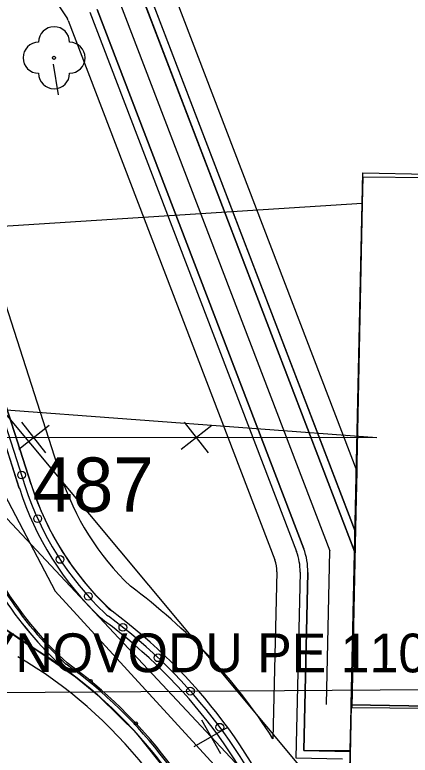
# Model space of a CAD drawing. Extents: x -643342 to -638635, y -1201752 to -1189948.
# Drawn here: x -639485.41 to -639472.65, y -1192704.29 to -1192680.44 of the extents above; entities that cross this region are included whole.
import ezdxf

# ---------------------------------------------------------------- set-up
doc = ezdxf.new("R2010")
doc.units = 0
for name, color, linetype in [('-zbytky_kruháče', 7, 'Continuous'), ('42', 7, 'Continuous'), ('IS_EL_NN_NADZEMNÍ', 7, 'Continuous'), ('IS_EL_NN_PODZEMNÍ', 7, 'Continuous'), ('K-HRANICE_KN', 7, 'Continuous'), ('K-SLUCKOVE CARY', 7, 'Continuous'), ('K-ČÍSLA_PARCEL', 7, 'Continuous'), ('N-CHODNIK', 7, 'Continuous'), ('N-CHODNIK-PŘÍMĚTICE', 7, 'Continuous'), ('N-OBVOD STAVBY 06', 7, 'Continuous'), ('N-oploceni', 7, 'Continuous'), ('N-rusene_vedeni', 7, 'Continuous'), ('N-SILNICE', 7, 'Continuous'), ('N-SRAFY_PLOCHY', 7, 'Continuous'), ('N-vo', 7, 'Continuous'), ('N-ZDI', 7, 'Continuous'), ('N-úprava plochu u obecního úřadu', 7, 'Continuous'), ('tomaštík - Džuganovi - Vrstva 36', 7, 'Continuous'), ('Z-budovy', 7, 'Continuous'), ('Z-hrany_a_čáry', 7, 'Continuous'), ('Z-stromy', 7, 'Continuous')]:
    doc.layers.add(name, color=color, linetype=linetype)

# ---------------------------------------------------------------- blocks, each defined once
blk = doc.blocks.new('zs')
at = {"layer": 'N-oploceni'}
blk.add_circle((0, 0), 0.05, dxfattribs=at)

msp = doc.modelspace()

# ---------------------------------------------------------------- linework, layer by layer
at = {"layer": '-zbytky_kruháče'}
msp.add_arc((-639492.588, -1192713.663), 14.5, 16.3969, 59.8841, dxfattribs=at)
at = {"layer": '42'}
msp.add_line((-639511.045, -1192702.433), (-639465.369, -1192702.13), dxfattribs=at)
at = {"layer": 'IS_EL_NN_NADZEMNÍ'}
msp.add_line((-639467.47, -1192716.07), (-639488.19, -1192693.98), dxfattribs=at)
msp.add_lwpolyline([(-639485.829, -1192693.153), (-639467.777, -1192714.748)], dxfattribs=at)
at = {"layer": 'IS_EL_NN_PODZEMNÍ'}
msp.add_line((-639489.5, -1192694.06), (-639474.67, -1192694.04), dxfattribs=at)
for points in [[(-639485.819, -1192693.156), (-639473.733, -1192694.06)], [(-639474.67, -1192694.04), (-639473.733, -1192694.06)]]:
    msp.add_lwpolyline(points, dxfattribs=at)
at = {"layer": 'K-HRANICE_KN'}
for p, q in [((-639474.18, -1192685.67), (-639474.2, -1192686.51)), ((-639463.27, -1192685.77), (-639474.18, -1192685.67)), ((-639474.2, -1192686.51), (-639490.92, -1192687.58))]:
    msp.add_line(p, q, dxfattribs=at)
at = {"layer": 'K-SLUCKOVE CARY'}
for p, q in [((-639474.2, -1192686.51), (-639474.54, -1192702.75)), ((-639474.54, -1192702.75), (-639457.62, -1192702.9))]:
    msp.add_line(p, q, dxfattribs=at)
at = {"layer": 'N-CHODNIK'}
for p, q in [((-639483.994, -1192683.015), (-639484.163, -1192682.029)), ((-639474.553, -1192702.67), (-639474.724, -1192710.703)), ((-639474.553, -1192702.67), (-639471.552, -1192702.72))]:
    msp.add_line(p, q, dxfattribs=at)
at = {"layer": 'N-CHODNIK-PŘÍMĚTICE'}
msp.add_line((-639488.992, -1192684.114), (-639485.26, -1192695.692), dxfattribs=at)
for centre, radius, start, end in [((-639475.742, -1192692.624), 10, 197.8667, 226.3544), ((-639475.742, -1192692.624), 12, 197.8667, 227.5242), ((-639475.742, -1192692.624), 11.85, 197.8667, 227.5242), ((-639481.678, -1192698.847), 1, 226.3544, 233.6318), ((-639481.678, -1192698.847), 1.4, 226.3544, 233.6318), ((-639492.588, -1192713.663), 17, 20.3626, 53.6318)]:
    msp.add_arc(centre, radius, start, end, dxfattribs=at)
at = {"layer": 'N-OBVOD STAVBY 06'}
msp.add_line((-639470.553, -1192702.741), (-639474.551, -1192702.67), dxfattribs=at)
for points in [[(-639486.272, -1192676.736), (-639483.707, -1192680.57)], [(-639474.551, -1192702.67), (-639474.362, -1192695.153), (-639480.414, -1192679.366)], [(-639483.682, -1192680.619), (-639477.02, -1192697.998)], [(-639483.927, -1192695.263), (-639487.659, -1192683.684)], [(-639476.954, -1192698.379), (-639477.078, -1192703.763)]]:
    msp.add_lwpolyline(points, dxfattribs=at)
for centre, radius, start, end in [((-639483.915, -1192680.709), 0.25, 21.0131, 33.7844), ((-639475.742, -1192692.624), 8.6, 197.8667, 226.3544), ((-639477.954, -1192698.356), 1, 358.6753, 20.9729), ((-639492.588, -1192713.663), 18.4, 32.5502, 53.6318)]:
    msp.add_arc(centre, radius, start, end, dxfattribs=at)
at = {"layer": 'N-oploceni'}
msp.add_lwpolyline([(-639488.802, -1192684.052), (-639485.069, -1192695.631)], dxfattribs=at)
for centre in [(-639485.187, -1192695.264), (-639484.667, -1192696.67), (-639483.946, -1192697.984), (-639483.033, -1192699.172), (-639481.92, -1192700.172), (-639480.785, -1192701.152), (-639479.741, -1192702.228), (-639478.793, -1192703.39)]:
    msp.add_circle(centre, 0.125, dxfattribs=at)
for centre, radius, start, end in [((-639475.742, -1192692.624), 9.8, 197.8667, 226.3544), ((-639475.742, -1192692.624), 11.8, 197.8667, 227.467), ((-639481.678, -1192698.847), 1.2, 226.3544, 233.6318), ((-639492.588, -1192713.663), 17.2, 20.3626, 53.6318), ((-639492.588, -1192713.663), 15.2, 20.3626, 54.302)]:
    msp.add_arc(centre, radius, start, end, dxfattribs=at)
at = {"layer": 'N-rusene_vedeni'}
for p, q in [((-639484.298, -1192693.668), (-639485.281, -1192694.44)), ((-639484.404, -1192694.545), (-639485.175, -1192693.562)), ((-639479.053, -1192693.668), (-639480.037, -1192694.44)), ((-639479.159, -1192694.545), (-639479.931, -1192693.562)), ((-639479.382, -1192703.154), (-639478.767, -1192704.242)), ((-639479.618, -1192704.006), (-639478.53, -1192703.391))]:
    msp.add_line(p, q, dxfattribs=at)
at = {"layer": 'N-SILNICE'}
for centre, radius, start, end in [((-639476.903, -1192688.091), 15, 205.9221, 238.4763), ((-639492.588, -1192713.663), 15, 20.3626, 58.4763), ((-639492.588, -1192713.663), 15.15, 20.3626, 54.3132)]:
    msp.add_arc(centre, radius, start, end, dxfattribs=at)
at = {"layer": 'N-SRAFY_PLOCHY'}
for p, q in [((-639474.431, -1192697.068), (-639481.114, -1192679.634)), ((-639474.439, -1192697.747), (-639481.348, -1192679.724)), ((-639481.348, -1192679.724), (-639474.439, -1192697.747)), ((-639482.981, -1192680.351), (-639476.32, -1192697.73)), ((-639482.748, -1192680.261), (-639476.086, -1192697.64)), ((-639476.086, -1192697.64), (-639482.748, -1192680.261)), ((-639485.26, -1192695.692), (-639488.992, -1192684.114)), ((-639487.126, -1192689.903), (-639485.26, -1192695.692)), ((-639484.879, -1192695.569), (-639486.745, -1192689.78)), ((-639474.439, -1192697.747), (-639474.431, -1192697.068)), ((-639474.584, -1192704.135), (-639474.439, -1192697.747)), ((-639475.954, -1192698.402), (-639476.087, -1192704.135)), ((-639476.087, -1192704.135), (-639475.954, -1192698.402)), ((-639482.508, -1192699.975), (-639482.644, -1192699.86)), ((-639482.644, -1192699.86), (-639482.508, -1192699.975)), ((-639482.508, -1192699.975), (-639482.508, -1192699.975)), ((-639484.745, -1192700.877), (-639485.791, -1192700.174)), ((-639484.745, -1192700.877), (-639483.845, -1192701.475)), ((-639483.445, -1192701.772), (-639484.745, -1192700.877)), ((-639482.675, -1192702.406), (-639483.445, -1192701.772)), ((-639481.458, -1192703.607), (-639482.675, -1192702.406)), ((-639474.552, -1192702.67), (-639474.724, -1192710.703)), ((-639471.552, -1192702.72), (-639474.552, -1192702.67)), ((-639480.316, -1192705.039), (-639481.458, -1192703.607)), ((-639476.087, -1192704.135), (-639474.584, -1192704.135)), ((-639474.584, -1192704.167), (-639476.087, -1192704.135)), ((-639474.688, -1192709.004), (-639474.584, -1192704.167))]:
    msp.add_line(p, q, dxfattribs=at)
msp.add_lwpolyline([(-639476.204, -1192698.396), (-639476.343, -1192704.379), (-639474.84, -1192704.412)], dxfattribs=at)
for centre, radius, start, end in [((-639476.903, -1192688.091), 15, 205.9221, 238.4763), ((-639475.84, -1192692.67), 9.492, 197.7857, 227.3573), ((-639475.742, -1192692.624), 10, 197.8667, 226.3544), ((-639475.742, -1192692.624), 10, 197.8667, 226.3544), ((-639475.741, -1192692.624), 12, 197.867, 227.5224), ((-639475.742, -1192692.624), 12, 197.8667, 227.5242), ((-639477.954, -1192698.356), 1.75, 358.6753, 20.9729), ((-639477.954, -1192698.356), 2, 358.6753, 20.9729), ((-639477.954, -1192698.356), 2, 358.6753, 20.9729), ((-639492.588, -1192713.663), 17.4, 20.3626, 53.6318), ((-639492.588, -1192713.663), 17, 20.3626, 53.6318), ((-639492.588, -1192713.663), 17, 20.3626, 53.6318), ((-639492.588, -1192713.663), 15, 20.3626, 54.3482)]:
    msp.add_arc(centre, radius, start, end, dxfattribs=at)
at = {"layer": 'N-vo'}
for p, q in [((-639487.486, -1192692.58), (-639484.101, -1192699.004)), ((-639484.101, -1192699.004), (-639476.892, -1192706.867))]:
    msp.add_line(p, q, dxfattribs=at)
at = {"layer": 'N-ZDI'}
msp.add_line((-639488.611, -1192683.991), (-639484.879, -1192695.569), dxfattribs=at)
for centre, radius, start, end in [((-639475.742, -1192692.624), 9.6, 197.8667, 226.3544), ((-639492.588, -1192713.663), 17.4, 20.3626, 53.6318)]:
    msp.add_arc(centre, radius, start, end, dxfattribs=at)
at = {"layer": 'N-úprava plochu u obecního úřadu'}
for p, q in [((-639474.431, -1192697.068), (-639474.439, -1192697.747)), ((-639476.087, -1192704.135), (-639474.584, -1192704.167))]:
    msp.add_line(p, q, dxfattribs=at)
for points in [[(-639481.114, -1192679.634), (-639474.431, -1192697.068)], [(-639481.348, -1192679.724), (-639474.439, -1192697.747), (-639474.553, -1192702.67)], [(-639482.982, -1192680.35), (-639476.32, -1192697.73)], [(-639482.748, -1192680.261), (-639476.086, -1192697.64)], [(-639476.204, -1192698.396), (-639476.343, -1192704.379), (-639474.84, -1192704.412)], [(-639475.954, -1192698.402), (-639476.087, -1192704.135)]]:
    msp.add_lwpolyline(points, dxfattribs=at)
for radius in [1.75, 2]:
    msp.add_arc((-639477.954, -1192698.356), radius, 358.6753, 20.9729, dxfattribs=at)
at = {"layer": 'Z-budovy'}
for p, q in [((-639474.552, -1192702.67), (-639474.183, -1192685.523)), ((-639474.183, -1192685.523), (-639470.184, -1192685.609)), ((-639459.845, -1192702.913), (-639474.552, -1192702.67))]:
    msp.add_line(p, q, dxfattribs=at)
at = {"layer": 'Z-hrany_a_čáry'}
for p, q in [((-639484.16, -1192674.47), (-639475.245, -1192697.704)), ((-639483.32, -1192674.6), (-639474.439, -1192697.747)), ((-639475.352, -1192702.653), (-639475.245, -1192697.704))]:
    msp.add_line(p, q, dxfattribs=at)
at = {"layer": 'Z-stromy'}
msp.add_circle((-639484.14, -1192681.82), 0.05, dxfattribs=at)
for centre, start, end in [((-639484.14, -1192681.32), 0, 180), ((-639484.64, -1192681.82), 90, 270), ((-639483.64, -1192681.82), 270, 90), ((-639484.14, -1192682.32), 180, 0)]:
    msp.add_arc(centre, 0.5, start, end, dxfattribs=at)

# ---------------------------------------------------------------- block references
at = {"layer": 'N-úprava plochu u obecního úřadu'}
for p, rotation in [((-639484.456, -1192700.58), -47.603199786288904), ((-639482.961, -1192701.901), -39.30084927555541), ((-639481.501, -1192703.266), -46.839767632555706)]:
    msp.add_blockref('zs', p, dxfattribs=dict(at, rotation=rotation))

# ---------------------------------------------------------------- texts
at = {"layer": 'K-ČÍSLA_PARCEL'}
msp.add_text('487', height=1.75, dxfattribs=at).set_placement((-639484.833, -1192696.449))
at = {"layer": 'tomaštík - Džuganovi - Vrstva 36'}
msp.add_text('ZASLEPENÍ STÁVAJÍCÍHO PLYNOVODU PE 110', height=1.25, rotation=359.9647, dxfattribs=at).set_placement((-639509.633, -1192701.6))

doc.saveas('drawing.dxf')
